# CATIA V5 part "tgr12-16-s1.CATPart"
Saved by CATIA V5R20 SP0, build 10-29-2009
Part number: TGR12-16-S1
Revision: 1
Definition: design
Nomenclature: TGR12-16-S1
Source: made
Description: NOT SPECIFIED
Bounding box of the stored display mesh (mm): x -22 to 0.8, y 0 to 12, z -6 to 6
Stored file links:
  C:\Users\Raffaele\Desktop\3D X SITO CF\I-MOLD\TGR-S1\tgr12-s1.step\tgr12-16-s1.CATPart
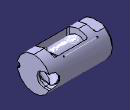
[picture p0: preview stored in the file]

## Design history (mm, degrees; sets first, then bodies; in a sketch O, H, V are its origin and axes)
Set1
  Line1 "LINE #4367": stored without definition
  DatumCurve1 "COMPOSITE_CURVE #4422"
  DatumCurve2 "COMPOSITE_CURVE #4471"
  DatumCurve3 "COMPOSITE_CURVE #4550"
  DatumCurve4 "COMPOSITE_CURVE #4593"
  DatumCurve5 "COMPOSITE_CURVE #4822"
  DatumCurve6 "COMPOSITE_CURVE #4963"
  DatumCurve7 "COMPOSITE_CURVE #4990"
  DatumCurve8 "COMPOSITE_CURVE #5048"
  DatumCurve9 "COMPOSITE_CURVE #5105"
  DatumCurve10 "COMPOSITE_CURVE #5134"
  DatumSurface1 "OPEN_SHELL #4357"
Body1 "MANIFOLD_SOLID_BREP #4358" (main body)
  Solid1: solid without history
